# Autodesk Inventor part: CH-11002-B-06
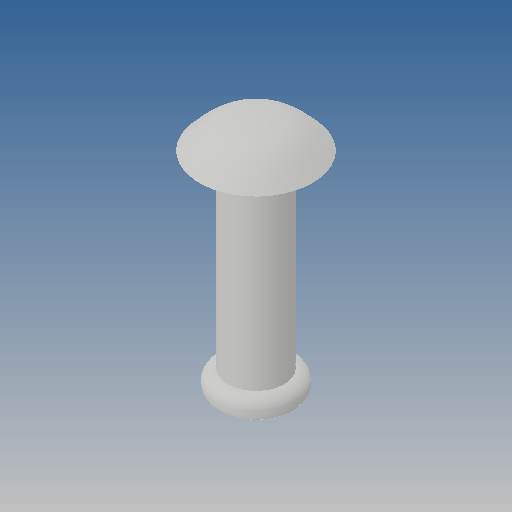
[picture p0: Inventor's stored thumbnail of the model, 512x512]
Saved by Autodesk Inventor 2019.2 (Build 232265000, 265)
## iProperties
Created: 2012-09
Part Number: CH-11002-B-06
Material: Ogólny
Document SubType Name: Modeling
Designer: CADENGINEERING4
Density: 1 g/cm^3
Appearance: Domyślna
Author: CADENGINEERING4
Revision Number: ÈÎºÎ
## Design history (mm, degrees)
feature "Ðý×ª1"
node "Bryła1"
